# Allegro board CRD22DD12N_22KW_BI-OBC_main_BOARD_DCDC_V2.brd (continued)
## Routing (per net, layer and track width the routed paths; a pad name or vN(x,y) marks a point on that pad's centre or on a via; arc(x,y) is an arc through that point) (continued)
N17792742: length 5.2
  TOP w0.508: C180.1 U20.1 ; C180.1 R131.2 ; C180.1 C179.1
N17792776: length 10.7
  TOP w0.508: v1(134.67,172.45) 134.8,172.32 R133.1 C181.1 137.16,171.94 138.43,170.67 U20.2 ; R132.2 v1(134.67,175.62)
  BOTTOM w0.508: v1(134.67,172.45) 135.51,173.29 135.51,174.79 v1(134.67,175.62)
N17792812: length 0.9
  TOP w0.508: U19.5 109.07,159.03 v1(108.97,159.13)
N17792937: length 0.9
  TOP w0.508: U20.5 135.1,159.03 v1(135,159.13)
N17820985: length 2.3
  BOTTOM w0.381: R36.2 R43.1
N17820987: length 2.3
  BOTTOM w0.381: R43.2 R48.1
N17935390: length 2.3
  BOTTOM w0.381: R52.2 R56.1
N17935392: length 2.3
  BOTTOM w0.381: R56.2 R65.1
N17935418: length 2.3
  BOTTOM w0.381: R53.2 R57.1
N17935420: length 2.3
  BOTTOM w0.381: R57.2 R66.1
N17935429: length 2.3
  BOTTOM w0.381: R49.2 R53.1
N17935432: length 2.3
  BOTTOM w0.381: R48.2 R52.1
N17977150: length 4.5
  BOTTOM w0.152: C131.2 R94.1 U12.1
N17977162: length 4.1
  BOTTOM w0.381: R94.2 33.02,82.67 C130.1 R92.2
N17977230: length 4.5
  BOTTOM w0.152: U12.16 C132.2 R93.1
N17977288: length 3.3
  BOTTOM w0.152: U12.2 R95.1
N17977296: length 3.3
  BOTTOM w0.152: U12.3 R97.1
N17977322: length 3.3
  BOTTOM w0.152: U12.4 R99.1
N17977346: length 3.3
  BOTTOM w0.152: U12.5 R101.1
N17977366: length 3.3
  BOTTOM w0.152: U12.15 R96.1
N17977368: length 3.3
  BOTTOM w0.152: U12.14 R98.1
N17977394: length 3.3
  BOTTOM w0.152: U12.13 R100.1
N17977396: length 3.3
  BOTTOM w0.152: U12.12 R102.1
N17990244: length 2.5
  BOTTOM w0.508: R34.1 17.14,24.26 R41.2
N17990246: length 2.3
  BOTTOM w0.381: R46.2 R41.1
N17990248: length 2.3
  BOTTOM w0.381: R50.2 R46.1
N17990300: length 2.3
  BOTTOM w0.381: R60.2 R54.1
N17990318: length 2.3
  BOTTOM w0.381: R69.2 R60.1
N17990348: length 2.3
  BOTTOM w0.381: R54.2 R50.1
N17998079: length 4.6
  TOP w0.381: R45.1 R39.2 6.22,154.94 6.62,155.34 U1.14
N18014670: length 2.3
  BOTTOM w0.381: R47.2 R42.1
N18014680: length 2.3
  BOTTOM w0.381: R51.2 R47.1
N18014712: length 2.3
  BOTTOM w0.381: R61.2 R55.1
N18014714: length 2.3
  BOTTOM w0.381: R70.2 R61.1
N18014716: length 2.3
  BOTTOM w0.381: R55.2 R51.1
N18080140: length 2.3
  TOP w0.762: R2.2 74.43,31.49 D1.1
N18080143: length 2.3
  TOP w0.762: D2.1 126.5,31.49 R1.1
N18080178: length 2.1
  TOP w0.762: R15.2 100.44,33.38 D7.1
N18080222: length 2.3
  TOP w0.762: D8.1 153.17,30.86 R14.1
N18096975: length 7.9
  TOP w0.381: D5.3 D9.3 CT5.1
N18096977: length 7.9
  TOP w0.381: D3.3 D10.3 CT1.1
N18097182: length 13.9
  TOP w0.381: CT8.1 72.39,81.92 66.8,81.92 64.9,80.01 D6.3
N18097184: length 13.9
  TOP w0.381: D4.3 64.9,83.82 66.8,85.72 72.39,85.72 CT7.1
N18143894: length 3.4
  TOP w0.381: D12.3 CT2.1
N18143920: length 3.4
  TOP w0.381: D11.3 CT6.1

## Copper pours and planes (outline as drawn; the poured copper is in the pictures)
-3V_PSW5 on BOTTOM (solid shape): 60.38,19.05 60.38,17.27 60.25,17.14 53.64,17.14 53.39,17.4 53.39,18.67 53.64,18.92 57.2,18.92 57.45,18.67 58.47,18.67 58.98,19.18 60.25,19.18
-3V_PSW6 on BOTTOM (solid shape): 86.41,19.05 86.41,17.27 86.28,17.14 79.68,17.14 79.43,17.4 79.43,18.67 79.68,18.92 83.24,18.92 83.49,18.67 84.51,18.67 85.01,19.18 86.28,19.18
-3V_PSW7 on BOTTOM (solid shape): 112.45,19.05 112.45,17.27 112.32,17.14 105.71,17.14 105.46,17.4 105.46,18.67 105.71,18.92 109.27,18.92 109.52,18.67 110.54,18.67 111.05,19.18 112.32,19.18
-3V_PSW8 on BOTTOM (solid shape): 138.48,19.05 138.48,17.27 138.35,17.14 131.75,17.14 131.5,17.4 131.5,18.67 131.75,18.92 135.31,18.92 135.56,18.67 136.58,18.67 137.08,19.18 138.35,19.18
-3V_PSW9 on BOTTOM (solid shape): 77.47,167.39 77.47,166.12 77.22,165.86 73.66,165.86 73.41,166.12 72.39,166.12 71.88,165.61 70.61,165.61 70.48,165.74 70.48,167.51 70.61,167.64 77.22,167.64
-3V_PSW10 on BOTTOM (solid shape): 103.5,167.39 103.5,166.12 103.25,165.86 99.69,165.86 99.44,166.12 98.42,166.12 97.92,165.61 96.65,165.61 96.52,165.74 96.52,167.51 96.65,167.64 103.25,167.64
-3V_PSW11 on BOTTOM (solid shape): 126.36,167.39 126.36,166.12 126.11,165.86 122.56,165.86 122.3,166.12 121.28,166.12 120.78,165.61 119.51,165.61 119.38,165.74 119.38,167.51 119.51,167.64 126.11,167.64
-3V_PSW12 on BOTTOM (solid shape): 152.4,167.39 152.4,166.12 152.15,165.86 148.59,165.86 148.34,166.12 147.32,166.12 146.81,165.61 145.54,165.61 145.41,165.74 145.41,167.51 145.54,167.64 152.15,167.64
AGND on TOP (solid shape): 49.53,2.41 150.88,2.41 151.13,2.16 151.13,1.27 12.06,1.27 11.68,1.65 11.68,3.3 11.81,3.43 48.51,3.43
AGND on TOP (solid shape): 9.4,161.8 9.4,159 9.27,158.88 6.35,158.88 5.21,160.02 4.19,160.02 4.06,160.15 4.06,161.54 4.57,162.05 9.14,162.05
AGND on TOP (solid shape): 72.64,15.51 72.64,10.94 72.14,10.43 65.79,10.43 65.66,10.56 65.66,11.19 65.79,11.32 70.99,11.32 71.63,11.96 71.63,13.48 70.99,14.11 68.71,14.11 68.33,14.5 68.33,15.77 68.45,15.89 72.26,15.89
AGND on TOP (solid shape): 124.71,15.51 124.71,10.94 124.21,10.43 117.86,10.43 117.73,10.56 117.73,11.19 117.86,11.32 123.06,11.32 123.7,11.96 123.7,13.48 123.06,14.11 120.78,14.11 120.4,14.5 120.4,15.77 120.52,15.89 124.33,15.89
AGND on TOP (solid shape): 150.75,15.51 150.75,10.94 150.24,10.43 143.89,10.43 143.76,10.56 143.76,11.19 143.89,11.32 149.1,11.32 149.73,11.96 149.73,13.48 149.1,14.11 146.81,14.11 146.43,14.5 146.43,15.77 146.56,15.89 150.37,15.89
AGND on TOP (solid shape): 98.78,15.51 98.78,10.94 98.28,10.43 91.93,10.43 91.8,10.56 91.8,11.19 91.93,11.32 97.13,11.32 97.77,11.96 97.77,13.48 97.13,14.11 94.72,14.11 94.34,14.5 94.34,15.77 94.47,15.89 98.4,15.89
AGND on BOTTOM (solid shape): 49.53,2.41 150.88,2.41 151.13,2.16 151.13,1.27 12.95,1.27 12.83,1.4 12.83,3.05 13.21,3.43 48.51,3.43
AGND on BOTTOM (solid shape): 62.03,12.7 62.03,9.27 61.9,9.14 60.63,9.14 59.87,9.91 53.52,9.91 53.26,10.16 53.26,12.57 53.52,12.83 61.9,12.83
AGND on BOTTOM (solid shape): 88.06,12.7 88.06,9.27 87.93,9.14 86.66,9.14 85.9,9.91 79.55,9.91 79.3,10.16 79.3,12.57 79.55,12.83 87.93,12.83
AGND on BOTTOM (solid shape): 114.1,12.7 114.1,9.27 113.97,9.14 112.7,9.14 111.94,9.91 105.59,9.91 105.33,10.16 105.33,12.57 105.59,12.83 113.97,12.83
AGND on BOTTOM (solid shape): 140.13,12.7 140.13,9.27 140,9.14 138.73,9.14 137.97,9.91 131.62,9.91 131.37,10.16 131.37,12.57 131.62,12.83 140,12.83
AGND on BOTTOM (solid shape): 30.48,70.23 33.91,70.23 35.05,69.09 35.05,60.83 34.67,60.45 32.38,60.45 32.13,60.71 32.13,61.34 33.15,62.36 33.15,66.93 32.64,67.44 29.46,67.44 28.83,66.8 28.83,65.15 28.45,64.77 21.84,64.77 21.59,65.02 21.59,72.01 21.84,72.26 28.45,72.26
AGND on GND02 (solid shape): outline of 4691 points within 1.27,1.27 151.64,93.47
P6.5V on BOTTOM (solid shape): 31.62,66.67 31.62,62.74 31.37,62.48 31.37,60.2 31.11,59.94 26.54,59.94 26.42,60.07 26.42,63.25 26.54,63.37 28.57,63.37 29.34,64.14 29.34,66.55 29.72,66.93 31.37,66.93
PGND on TOP (solid shape): 93.6,35.69 93.6,34.16 93.34,33.91 90.68,33.91 90.17,33.4 90.17,29.59 89.66,29.08 88.01,29.08 87.63,29.46 87.63,35.56 88.14,36.07 93.22,36.07
PGND on TOP (solid shape): 145.67,35.81 145.67,34.29 145.41,34.04 142.75,34.04 142.24,33.53 142.24,29.72 141.73,29.21 140.08,29.21 139.7,29.59 139.7,35.69 140.21,36.2 145.29,36.2
PGND on BOTTOM (solid shape): 59.56,55.75 59.56,49.53 54.93,44.89 29.78,44.89 28.96,45.72 28.96,57.28 29.84,58.17 57.15,58.17
PGND on GND02 (solid shape): outline of 2011 points within 10.03,8.76 151.64,58.93
SGND on TOP (solid shape): 53.09,174.37 53.09,172.47 54.1,171.45 54.1,170.56 54.36,170.31 54.36,165.86 53.98,165.48 51.05,165.48 50.8,165.74 50.8,169.93 51.05,170.18 51.05,171.32 51.18,171.45 51.82,171.45 52.45,172.09 52.45,174.37 52.58,174.5 52.96,174.5
SGND on TOP (solid shape): 91.24,174.23 91.24,173.59 91.11,173.46 86.03,173.46 85.22,172.65 85.22,171.43 85.98,170.67 88.19,170.67 88.57,170.29 88.57,169.02 88.44,168.89 84.63,168.89 84.25,169.27 84.25,173.85 84.76,174.35 91.11,174.35
SGND on TOP (solid shape): 114.1,174.23 114.1,173.59 113.97,173.46 108.89,173.46 108.08,172.65 108.08,171.43 108.84,170.67 111.05,170.67 111.43,170.29 111.43,169.02 111.3,168.89 107.49,168.89 107.11,169.27 107.11,173.85 107.62,174.35 113.97,174.35
SGND on TOP (solid shape): 140.13,174.23 140.13,173.59 140,173.46 134.92,173.46 134.11,172.65 134.11,171.43 134.87,170.67 137.08,170.67 137.46,170.29 137.46,169.02 137.34,168.89 133.53,168.89 133.15,169.27 133.15,173.85 133.65,174.35 140,174.35
SGND on TOP (solid shape): 65.2,174.23 65.2,173.59 65.07,173.46 60.07,173.46 59.69,173.08 59.56,173.08 59.05,172.58 59.05,171.69 59.69,171.05 62.1,171.05 62.61,170.54 62.61,169.02 62.36,168.77 58.17,168.77 57.87,169.06 57.87,172.61 59.61,174.35 65.07,174.35
SGND on BOTTOM (solid shape): 70.99,174.88 77.34,174.88 77.6,174.62 77.6,172.21 77.34,171.96 68.96,171.96 68.83,172.09 68.83,175.51 68.96,175.64 70.23,175.64
SGND on BOTTOM (solid shape): 97.03,174.88 103.38,174.88 103.63,174.62 103.63,172.21 103.38,171.96 95,171.96 94.87,172.09 94.87,175.51 95,175.64 96.27,175.64
SGND on BOTTOM (solid shape): 119.89,174.88 126.24,174.88 126.49,174.62 126.49,172.21 126.24,171.96 117.86,171.96 117.73,172.09 117.73,175.51 117.86,175.64 119.13,175.64
SGND on BOTTOM (solid shape): 145.92,174.88 152.27,174.88 152.53,174.62 152.53,172.21 152.27,171.96 143.89,171.96 143.76,172.09 143.76,175.51 143.89,175.64 145.16,175.64
SGND on GND02 (solid shape): outline of 3201 points within 1.27,94.49 153.54,178.73
DCINPUT on TOP (solid shape): outline of 560 points within 16.13,11.3 153.23,57.53
DCINPUT on BOTTOM (solid shape): 58.04,34.29 58.04,33.53 58.8,32.77 58.8,29.72 58.17,29.08 49.91,29.08 44.83,24 37.32,24 33,23.02 30.68,19.25 30.35,18.92 30.35,12.57 29.21,11.43 17.78,11.43 16,13.21 16,19.88 16.38,20.26 19.88,20.26 25.34,25.72 25.34,33.34 28.96,36.96 55.37,36.96
DCINPUT on POWER03 (solid shape): outline of 404 points within 16.76,11.94 111.19,61.59
DRVA_G on BOTTOM (solid shape): 58.55,21.59 63.37,21.59 63.5,21.46 63.5,17.65 63.37,17.53 61.9,17.53 61.77,17.65 61.77,19.43 61.52,19.68 58.6,19.68 58.34,19.43 53.77,19.43 53.52,19.68 53.52,21.46 53.9,21.84 58.29,21.84
DRVB_G on BOTTOM (solid shape): 84.58,21.59 89.39,21.59 89.51,21.46 89.51,17.65 89.39,17.53 87.93,17.53 87.81,17.65 87.81,19.43 87.55,19.68 84.63,19.68 84.38,19.43 79.81,19.43 79.55,19.68 79.55,21.46 79.93,21.84 84.33,21.84
DRVC_G on BOTTOM (solid shape): 110.62,21.59 115.32,21.59 115.57,21.34 115.57,17.65 115.44,17.53 113.97,17.53 113.84,17.65 113.84,19.43 113.59,19.68 110.67,19.68 110.41,19.43 105.84,19.43 105.59,19.68 105.59,21.46 105.97,21.84 110.36,21.84
DRVD_G on BOTTOM (solid shape): 136.65,21.59 141.35,21.59 141.6,21.34 141.6,17.65 141.48,17.53 140,17.53 139.88,17.65 139.88,19.43 139.62,19.68 136.7,19.68 136.45,19.43 131.88,19.43 131.62,19.68 131.62,21.46 132,21.84 136.4,21.84
LEGA on BOTTOM (solid shape): outline of 408 points within 61.72,28.57 106.68,67.82
LEGB on TOP (solid shape): 169.29,46.23 169.29,26.92 168.66,26.29 158.37,26.29 157.99,26.67 157.99,46.61 159.64,48.26 167.26,48.26
LEGB on BOTTOM (solid shape): 148.07,48.26 152.23,46.51 156.39,48.26 167.26,48.26 169.29,46.23 169.29,26.92 168.67,26.3 167.65,26.3 167.64,26.29 167.62,26.29 158.39,26.29 158.37,26.29 158.35,26.3 157.49,27.16 157.48,27.18 157.48,27.2 157.48,34.8 153.03,39.24 144.08,39.24 141.99,37.15 138.87,37.15 137.16,35.43 137.16,29.21 136.91,28.96 133.22,28.96 132.97,29.21 132.97,37.85 135.13,40.01 135.13,44.07 139.32,48.26
LEGB on GND02 (solid shape): 169.29,46.23 169.29,26.92 168.66,26.29 158.37,26.29 157.99,26.67 157.99,46.61 159.64,48.26 167.26,48.26
LEGB on POWER03 (solid shape): outline of 184 points within 113.88,26.92 168.15,48.77
SLEGA on TOP (solid shape): 167.26,164.97 167.26,129.54 165.99,128.27 159.26,128.27 158.5,129.03 158.5,164.85 159.64,165.99 166.24,165.99
SLEGA on BOTTOM (solid shape): 167.26,164.97 167.26,129.54 165.99,128.27 159.26,128.27 158.5,129.03 158.5,164.85 159.64,165.99 166.24,165.99
SLEGA on GND02 (solid shape): 167.26,164.97 167.26,129.54 165.99,128.27 159.26,128.27 158.5,129.03 158.5,164.85 159.64,165.99 166.24,165.99
SLEGA on POWER03 (solid shape): outline of 325 points within 66.93,128.27 167.26,165.99
SLEGB on BOTTOM (solid shape): outline of 420 points within 107.19,115.57 153.16,155.96
SLEGB on GND02 (solid shape): 153.18,121.54 153.18,115.95 152.67,115.44 128.55,115.44 128.53,115.45 128.51,115.46 128.16,115.81 128.15,115.83 128.14,115.85 128.14,121.54 129.03,122.43 152.29,122.43
SLEGB on POWER03 (solid shape): 153.18,121.54 153.18,115.95 152.67,115.44 128.55,115.44 128.53,115.45 128.51,115.46 128.16,115.81 128.15,115.83 128.14,115.85 128.14,121.54 129.03,122.43 152.29,122.43
SPGND on TOP (solid shape): 95.5,148.97 94.74,148.21 89.53,148.21 89.28,148.46 89.28,150.75 89.66,151.13 92.58,151.13 92.84,151.38 92.84,155.83 93.22,156.21 95.5,156.21
SPGND on TOP (solid shape): 144.15,155.96 144.15,148.59 143.64,148.08 138.56,148.08 138.56,150.37 138.94,150.75 141.22,150.75 141.73,151.26 141.73,155.83 142.11,156.21 143.89,156.21
SPGND on TOP (solid shape): 43.88,173.55 44.01,173.55 45.21,172.34 45.21,164.21 49.91,159.51 49.91,157.61 49.02,156.72 47.37,156.72 41.66,162.43 32.51,162.43 31.24,163.7 31.24,172.59 32.51,173.86 43.56,173.86
SPGND on BOTTOM (solid shape): 44.96,173.1 44.96,164.85 49.66,160.15 49.66,157.48 48.64,156.46 46.86,156.46 43.94,159.38 33.02,159.38 31.24,161.16 31.24,173.1 32.13,173.99 44.07,173.99
SPGND on BOTTOM (solid shape): 36.58,119.38 50.8,119.38 51.18,119 51.18,106.68 50.55,106.05 38.73,106.05 37.97,106.81 37.97,111 37.34,111.63 28.45,111.63 27.69,112.39 27.69,120.27 28.32,120.9 35.05,120.9
SPGND on GND02 (solid shape): outline of 2003 points within 9.4,106.05 146.56,172.85
SRA_G on BOTTOM (solid shape): 69.09,167.13 69.09,165.35 69.34,165.1 72.26,165.1 72.52,165.35 77.09,165.35 77.34,165.1 77.34,163.32 76.96,162.94 72.57,162.94 72.31,163.19 67.56,163.19 67.44,163.32 67.44,167.13 67.56,167.26 68.96,167.26
SRB_G on BOTTOM (solid shape): 95.12,167.13 95.12,165.35 95.38,165.1 98.3,165.1 98.55,165.35 103.12,165.35 103.38,165.1 103.38,163.32 103,162.94 98.6,162.94 98.35,163.19 93.6,163.19 93.47,163.32 93.47,167.13 93.6,167.26 95,167.26
SRC_G on BOTTOM (solid shape): 117.98,167.13 117.98,165.35 118.24,165.1 121.16,165.1 121.41,165.35 125.98,165.35 126.24,165.1 126.24,163.32 125.86,162.94 121.46,162.94 121.21,163.19 116.46,163.19 116.33,163.32 116.33,167.13 116.46,167.26 117.86,167.26
SRD_G on BOTTOM (solid shape): 144.02,167.13 144.02,165.35 144.27,165.1 147.19,165.1 147.45,165.35 152.02,165.35 152.27,165.1 152.27,163.32 151.89,162.94 147.5,162.94 147.24,163.19 142.49,163.19 142.37,163.32 142.37,167.13 142.49,167.26 143.89,167.26
VO+ on TOP (solid shape): outline of 688 points within 11.68,123.57 149.99,156.99
VO+ on BOTTOM (solid shape): outline of 313 points within 10.41,105.92 92.33,156.46
VO+ on POWER03 (solid shape): outline of 238 points within 10.29,126.75 54.99,148.02
VP+5V on BOTTOM (solid shape): 23.5,62.99 23.5,56.64 23.24,56.39 16.26,56.39 13.53,53.66 12.32,53.66 12.13,53.85 12.13,55.56 15.11,58.55 20.32,58.55 21.84,60.07 21.84,62.99 21.97,63.12 23.37,63.12
VP+5V on POWER03 (solid shape): outline of 359 points within 2.54,24.64 13.97,55.37
VP+15V on TOP (solid shape): 79.54,8.51 80.27,7.14 80.99,8.51 105.57,8.51 106.3,7.14 107.03,8.51 131.61,8.51 132.34,7.14 133.06,8.51 143.64,8.51 143.76,8.38 143.76,5.08 143.38,4.7 64.9,4.7 64.39,5.21 64.39,8.26 64.64,8.51
VP+15V on BOTTOM (solid shape): 65.58,12.19 65.58,6.48 65.46,6.35 62.92,6.35 62.79,6.48 62.79,8.64 62.66,8.76 62.66,9.65 63.55,10.54 63.55,12.32 63.68,12.45 65.33,12.45
VP+15V on BOTTOM (solid shape): 91.62,12.19 91.62,6.48 91.49,6.35 88.95,6.35 88.82,6.48 88.82,8.64 88.7,8.76 88.7,9.65 89.59,10.54 89.59,12.32 89.71,12.45 91.36,12.45
VP+15V on BOTTOM (solid shape): 117.65,12.19 117.65,6.48 117.53,6.35 114.99,6.35 114.86,6.48 114.86,8.64 114.73,8.76 114.73,9.65 115.62,10.54 115.62,12.32 115.75,12.45 117.4,12.45
VP+15V on BOTTOM (solid shape): 143.69,12.19 143.69,6.48 143.56,6.35 141.02,6.35 140.89,6.48 140.89,8.64 140.77,8.76 140.77,9.65 141.66,10.54 141.66,12.32 141.78,12.45 143.43,12.45
VP+15V_DCDCA on BOTTOM (solid shape): 65.84,23.62 66.73,23.62 66.85,23.5 66.85,22.35 66.73,22.23 64.14,22.23 63.37,22.99 58.8,22.99 58.29,22.48 53.39,22.48 53.26,22.61 53.26,24.38 53.52,24.64 64.82,24.64
VP+15V_DCDCB on BOTTOM (solid shape): 91.87,23.62 92.76,23.62 92.89,23.5 92.89,22.35 92.76,22.23 90.17,22.23 89.41,22.99 84.84,22.99 84.33,22.48 79.43,22.48 79.3,22.61 79.3,24.38 79.55,24.64 90.86,24.64
VP+15V_DCDCC on BOTTOM (solid shape): 117.91,23.62 118.8,23.62 118.92,23.5 118.92,22.35 118.8,22.23 116.2,22.23 115.44,22.99 110.87,22.99 110.36,22.48 105.46,22.48 105.33,22.61 105.33,24.38 105.59,24.64 116.89,24.64
VP+15V_DCDCD on BOTTOM (solid shape): 143.94,23.62 144.83,23.62 144.96,23.5 144.96,22.35 144.83,22.23 142.24,22.23 141.48,22.99 136.91,22.99 136.4,22.48 131.5,22.48 131.37,22.61 131.37,24.38 131.62,24.64 142.93,24.64
VS+5V on TOP (solid shape): 51.56,173.61 51.56,172.21 51.31,171.96 50.55,171.96 50.29,171.7 50.29,170.81 49.4,169.93 49.4,165.74 49.02,165.35 47.24,165.35 46.86,165.74 46.86,173.35 47.24,173.74 51.44,173.74
VS+15V on TOP (solid shape): outline of 248 points within 53.98,168.28 141.48,178.73
VS+15V on BOTTOM (solid shape): 68.07,178.31 68.07,176.15 68.2,176.02 68.2,175.13 67.31,174.24 67.31,172.47 67.18,172.34 65.53,172.34 65.28,172.59 65.28,178.31 65.41,178.44 67.94,178.44
VS+15V on BOTTOM (solid shape): 94.11,178.31 94.11,176.15 94.23,176.02 94.23,175.13 93.34,174.24 93.34,172.47 93.22,172.34 91.57,172.34 91.31,172.59 91.31,178.31 91.44,178.44 93.98,178.44
VS+15V on BOTTOM (solid shape): 116.97,178.31 116.97,176.15 117.09,176.02 117.09,175.13 116.2,174.24 116.2,172.47 116.08,172.34 114.43,172.34 114.17,172.59 114.17,178.31 114.3,178.44 116.84,178.44
VS+15V on BOTTOM (solid shape): 143,178.31 143,176.15 143.13,176.02 143.13,175.13 142.24,174.24 142.24,172.47 142.11,172.34 140.46,172.34 140.21,172.59 140.21,178.31 140.34,178.44 142.88,178.44
VS+15V_DCDCA on BOTTOM (solid shape): 77.47,162.18 77.47,160.53 77.09,160.15 67.69,160.15 66.93,159.38 64.14,159.38 64.01,159.51 64.01,160.66 64.14,160.78 66.29,160.78 67.31,161.8 72.01,161.8 72.52,162.31 77.34,162.31
VS+15V_DCDCB on BOTTOM (solid shape): 103.63,162.18 103.63,160.4 103.38,160.15 93.09,160.15 92.33,159.38 90.17,159.38 90.04,159.51 90.04,160.66 90.17,160.78 91.69,160.78 92.71,161.8 93.47,161.8 93.5,161.82 93.52,161.8 98.09,161.8 98.6,162.31 103.5,162.31
VS+15V_DCDCC on BOTTOM (solid shape): 126.49,162.18 126.49,160.4 126.24,160.15 116.64,160.15 115.8,159.31 113.06,159.31 112.9,159.46 112.9,160.88 113.06,161.04 115.62,161.04 116.38,161.8 120.95,161.8 121.46,162.31 126.36,162.31
VS+15V_DCDCD on BOTTOM (solid shape): 152.53,162.18 152.53,160.4 152.27,160.15 142.88,160.15 141.99,159.26 139.06,159.26 138.94,159.38 138.94,160.53 139.19,160.78 141.35,160.78 142.37,161.8 146.99,161.8 147.5,162.31 152.4,162.31
N16123922 on TOP (solid shape): 27.05,173.48 27.05,158.5 26.16,157.61 16.64,157.61 16.26,157.99 16.26,158.75 16.19,158.81 16.19,161.99 16.76,162.56 18.41,162.56 18.41,162.94 16.76,162.94 15.75,163.96 13.46,163.96 12.95,164.47 12.95,173.74 13.46,174.24 26.29,174.24
N16123922 on BOTTOM (solid shape): 27.05,172.59 27.05,165.99 25.02,163.96 12.95,163.96 12.32,164.59 12.32,172.09 13.59,173.35 26.29,173.35
N16148550 on TOP (solid shape): 33.4,139.19 33.4,126.11 32.77,125.48 9.91,125.48 9.53,125.86 9.53,138.56 10.67,139.7 32.89,139.7
N17453412 on BOTTOM (solid shape): 103.5,178.18 103.5,175.9 103.25,175.64 97.28,175.64 96.39,176.53 95.38,176.53 95.12,176.78 95.12,178.31 95.25,178.44 103.25,178.44
N17453587 on BOTTOM (solid shape): 77.47,178.18 77.47,175.9 77.22,175.64 71.25,175.64 70.36,176.53 69.34,176.53 69.09,176.78 69.09,178.31 69.22,178.44 77.22,178.44
N17454238 on BOTTOM (solid shape): 60.5,8.26 61.52,8.26 61.77,8 61.77,6.48 61.65,6.35 53.64,6.35 53.39,6.6 53.39,8.89 53.64,9.14 59.61,9.14
N17454469 on BOTTOM (solid shape): 86.54,8.26 87.55,8.26 87.81,8 87.81,6.48 87.68,6.35 79.68,6.35 79.43,6.6 79.43,8.89 79.68,9.14 85.65,9.14
N17785767 on BOTTOM (solid shape): 71.12,25.83 71.12,24.13 70.87,23.88 69.47,23.88 69.39,23.8 69.39,22.35 69.27,22.23 67.92,22.23 67.87,22.28 67.87,25.78 68.12,26.04 70.92,26.04
N17785926 on BOTTOM (solid shape): 97.16,25.83 97.16,24.13 96.9,23.88 95.5,23.88 95.43,23.8 95.43,22.35 95.3,22.23 93.95,22.23 93.9,22.28 93.9,25.78 94.16,26.04 96.95,26.04
N17788345 on BOTTOM (solid shape): 123.19,25.83 123.19,24.13 122.94,23.88 121.54,23.88 121.46,23.8 121.46,22.35 121.34,22.23 119.99,22.23 119.94,22.28 119.94,25.78 120.19,26.04 122.99,26.04
N17788478 on BOTTOM (solid shape): 149.22,25.83 149.22,24.13 148.97,23.88 147.57,23.88 147.5,23.8 147.5,22.35 147.37,22.23 146.02,22.23 145.97,22.28 145.97,25.78 146.23,26.04 149.02,26.04
N17790484 on BOTTOM (solid shape): 62.99,162.51 62.99,159 62.74,158.75 59.94,158.75 59.74,158.95 59.74,160.66 59.99,160.91 61.39,160.91 61.47,160.99 61.47,162.43 61.59,162.56 62.94,162.56
N17790617 on BOTTOM (solid shape): 89.03,162.51 89.03,159 88.77,158.75 85.98,158.75 85.78,158.95 85.78,160.66 86.03,160.91 87.43,160.91 87.5,160.99 87.5,162.43 87.63,162.56 88.98,162.56
N17792812 on BOTTOM (solid shape): 111.89,162.51 111.89,159 111.63,158.75 108.84,158.75 108.64,158.95 108.64,160.66 108.89,160.91 110.29,160.91 110.36,160.99 110.36,162.43 110.49,162.56 111.84,162.56
N17792937 on BOTTOM (solid shape): 137.92,162.51 137.92,159 137.67,158.75 134.87,158.75 134.67,158.95 134.67,160.66 134.92,160.91 136.32,160.91 136.4,160.99 136.4,162.43 136.53,162.56 137.87,162.56
N17962871 on BOTTOM (solid shape): 112.57,8.26 113.59,8.26 113.84,8 113.84,6.48 113.72,6.35 105.71,6.35 105.46,6.6 105.46,8.89 105.71,9.14 111.68,9.14
N17963706 on BOTTOM (solid shape): 138.61,8.26 139.62,8.26 139.88,8 139.88,6.48 139.75,6.35 131.75,6.35 131.5,6.6 131.5,8.89 131.75,9.14 137.72,9.14
N17964909 on BOTTOM (solid shape): 126.36,178.18 126.36,175.9 126.11,175.64 120.14,175.64 119.25,176.53 118.24,176.53 117.98,176.78 117.98,178.31 118.11,178.44 126.11,178.44
N17965565 on BOTTOM (solid shape): 152.4,178.18 152.4,175.9 152.15,175.64 146.18,175.64 145.29,176.53 144.27,176.53 144.02,176.78 144.02,178.31 144.15,178.44 152.15,178.44
N17988090 on TOP (solid shape): 202.44,52.83 202.44,47.62 200.91,46.1 191.52,46.1 190.88,45.47 190.88,27.3 189.99,26.42 180.95,26.42 179.83,27.53 179.83,52.7 180.97,53.85 201.42,53.85
N17988090 on BOTTOM (solid shape): 202.44,52.83 202.44,47.62 200.91,46.1 191.52,46.1 190.88,45.47 190.88,27.3 189.99,26.42 180.95,26.42 179.83,27.53 179.83,52.7 180.97,53.85 201.42,53.85
N17988090 on GND02 (solid shape): 202.44,52.83 202.44,47.62 200.91,46.1 191.52,46.1 190.88,45.47 190.88,27.3 189.99,26.42 180.95,26.42 179.83,27.53 179.83,52.7 180.97,53.85 201.42,53.85
N17988090 on POWER03 (solid shape): 202.44,52.83 202.44,47.62 200.91,46.1 191.52,46.1 190.88,45.47 190.88,27.3 189.99,26.42 180.95,26.42 179.83,27.53 179.83,52.7 180.97,53.85 201.42,53.85
N17988199 on TOP (solid shape): 189.61,164.97 189.61,137.79 192.28,135.13 199.52,135.13 201.04,133.6 201.04,128.91 199.66,127.52 186.49,127.52 186.48,127.51 186.46,127.51 178.82,127.51 177.55,128.78 177.55,164.85 178.69,165.99 188.59,165.99
N17988199 on BOTTOM (solid shape): 189.61,164.97 189.61,137.79 192.28,135.13 199.52,135.13 201.04,133.6 201.04,128.91 199.66,127.52 186.49,127.52 186.48,127.51 186.46,127.51 178.82,127.51 177.55,128.78 177.55,164.85 178.69,165.99 188.59,165.99
N17988199 on GND02 (solid shape): 189.61,164.97 189.61,137.79 192.28,135.13 199.52,135.13 201.04,133.6 201.04,128.91 199.66,127.52 186.49,127.52 186.48,127.51 186.46,127.51 178.82,127.51 177.55,128.78 177.55,164.85 178.69,165.99 188.59,165.99
N17988199 on POWER03 (solid shape): 189.61,164.97 189.61,137.79 192.28,135.13 199.52,135.13 201.04,133.6 201.04,128.91 199.66,127.52 186.49,127.52 186.48,127.51 186.46,127.51 178.82,127.51 177.55,128.78 177.55,164.85 178.69,165.99 188.59,165.99
N17988317 on TOP (solid shape): 235.08,132.97 235.08,116.71 234.06,115.7 169.29,115.7 168.4,116.59 168.4,121.41 169.29,122.3 215.14,122.3 226.44,133.6 234.44,133.6
N17988317 on BOTTOM (solid shape): 235.08,132.97 235.08,116.71 234.06,115.7 169.29,115.7 168.4,116.59 168.4,121.41 169.29,122.3 215.14,122.3 226.44,133.6 234.44,133.6
N17988317 on GND02 (solid shape): 235.08,132.97 235.08,116.71 234.06,115.7 169.29,115.7 168.4,116.59 168.4,121.41 169.29,122.3 215.14,122.3 226.44,133.6 234.44,133.6
N17988317 on POWER03 (solid shape): 235.08,132.97 235.08,116.71 234.06,115.7 169.29,115.7 168.4,116.59 168.4,121.41 169.29,122.3 215.14,122.3 226.44,133.6 234.44,133.6
N17997979 on TOP (solid shape): 4.06,155.07 4.06,154.43 4.19,154.31 9.14,154.31 9.4,154.05 9.4,152.65 9.14,152.4 6.22,152.4 5.84,152.78 1.91,152.78 1.65,153.03 1.65,155.07 1.78,155.19 3.94,155.19
N18067595 on TOP (solid shape): 235.15,66.22 235.15,47.62 234.31,46.79 234.31,46.74 225.68,46.74 224.09,48.32 224.09,53.53 215.9,61.72 215.9,66.93 216.79,67.82 233.55,67.82
N18067595 on BOTTOM (solid shape): 235.15,66.22 235.15,47.62 234.31,46.79 234.31,46.74 225.68,46.74 225.68,52.2 221.74,56.13 221.23,56.13 215.9,61.47 215.9,66.93 216.79,67.82 233.55,67.82
N18067595 on GND02 (solid shape): 235.15,66.22 235.15,47.62 234.31,46.79 234.31,46.74 225.68,46.74 215.9,56.52 215.9,66.93 216.79,67.82 233.55,67.82
N18067595 on POWER03 (solid shape): 235.15,66.22 235.15,47.62 234.31,46.79 234.31,46.74 225.68,46.74 215.9,56.52 215.9,66.93 216.79,67.82 233.55,67.82
N18126472 on BOTTOM (solid shape): 187.58,67.31 187.58,61.59 186.82,60.83 135.38,60.83 134.75,61.47 134.75,67.56 135.25,68.07 186.82,68.07
N18126472 on GND02 (solid shape): 187.58,67.31 187.58,61.59 186.82,60.83 135.38,60.83 134.75,61.47 134.75,67.56 135.25,68.07 186.82,68.07

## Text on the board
BOTTOM: ARTWORK BOTTOM
Board Geometry/Soldermask Bottom: SOLDERMASK BOTTOM
Package Geometry/Pastemask Bottom: PASTEMASK BOTTOM
Ref Des/Silkscreen Bottom: SILKSCREEN BOTTOM
TOP: ARTWORK TOP
Board Geometry/Soldermask Top: SOLDERMASK TOP
Package Geometry/Pastemask Top: PASTEMASK TOP
Ref Des/Silkscreen Top: CRD22DD12N_22KW_BI-OBC_MAIN_BOARD | Rev B 1020 | SILKSCREEN TOP
GND02: ARTWORK LAYER02
POWER03: ARTWORK LAYER03
DIMENSION: Board Cut Out | Board Name : | Dielectric Material : | Surface  Finished : | FR4 | Board Thickness : | Spell   Mode  : | 2.00mm +/- 10% | 1 X 1 | Layers : | Board Cut Out : | 4 | Purchase Order & Specification Sheet | FAB DRAWING
COMPVAL_TYPE_BOTTOM: PRIMARY SIDE
ASSEMBLY_BOTTOM: SECONDARY SIDE
User.17: FIGURE | SIZE | 12.0 | 32.0 | 39.0 | 40.0 | 47.0 | 59.06 | 67.0 | 87.0 | 122.0 | 236.0 | 295.0x118.0 | 315.0x157.0 | 315.0x158.0 | DRILL CHART: TOP to BOTTOM | ALL UNITS ARE IN MILS | TOLERANCE | +0.0/-0.0 | +3.0/-3.0 | PLATED | NON-PLATED | QTY | 199 | 4 | 62 | 55 | 3 | 11 | 8 | 32 | 16 | 7 | 10 | 12 | 2
